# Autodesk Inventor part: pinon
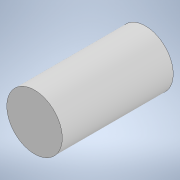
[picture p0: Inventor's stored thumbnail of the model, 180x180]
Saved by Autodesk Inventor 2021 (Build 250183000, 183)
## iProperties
Created: 2021-07
Part Number: pinon
Material: Generic
Document SubType Name: Modeling
Designer: adams
Density: 1 g/cm^3
Appearance: Default
Author: adams
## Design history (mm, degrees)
sketch "Sketch2"
  geometry: C1 r 6.35 at (-4.523, 4.062); 1 further point
  constraints: 1 centre point
  dimensions: "d3" = 12.7 dimension on point (0, 0) C1.centre C1; "d3" = 12.7 diameter of C1
extrude "Extrusion2" new body sketch "Sketch2" distance "d4" = 25.4; taper "d5" = 0 deg
body "Solid2"
